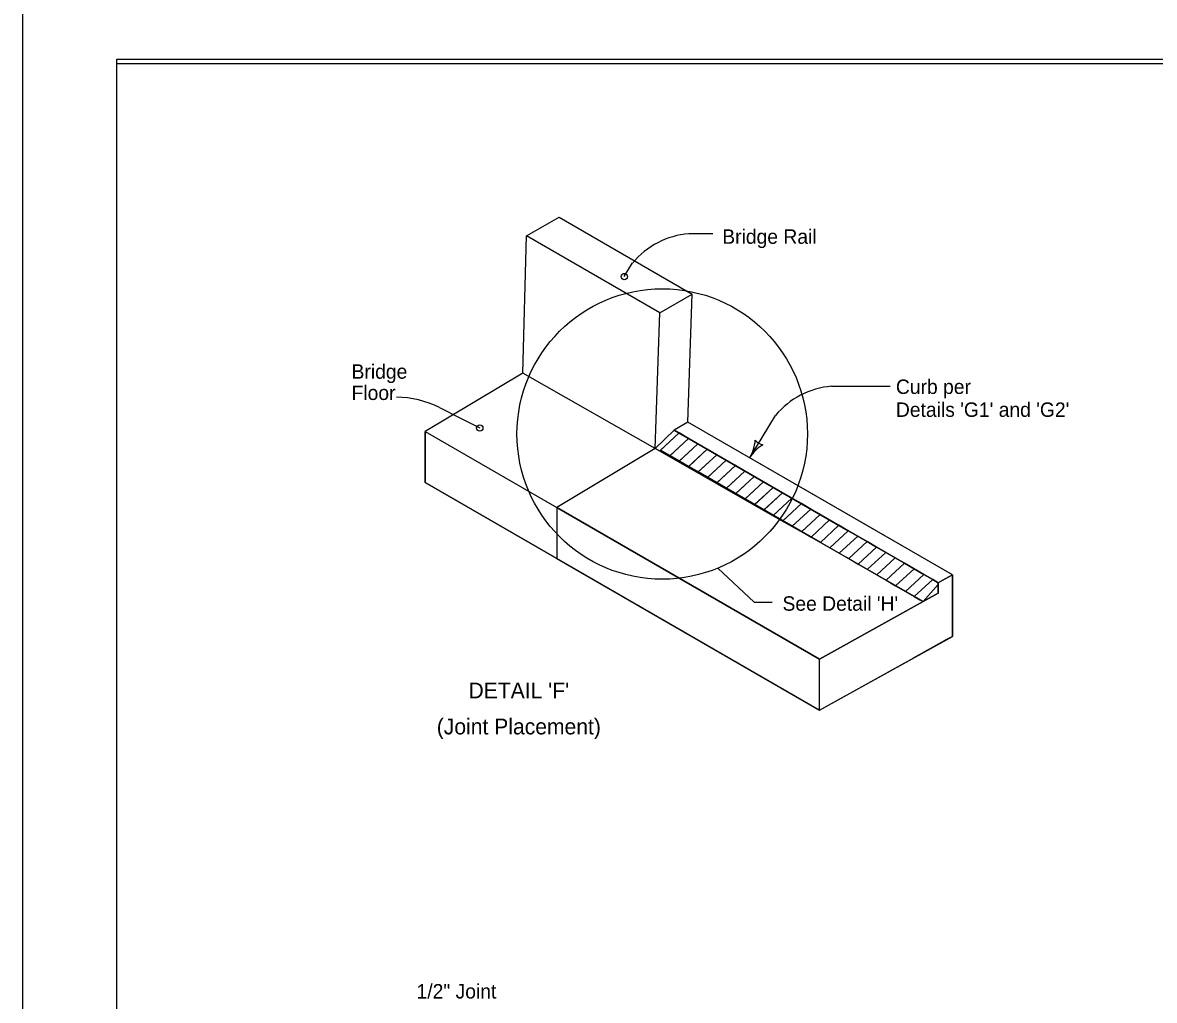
# Model space of a CAD drawing. Extents: x 10028 to 81668, y 6395 to 11634.
# Drawn here: x 24428 to 25683, y 8900 to 9984 of the extents above; entities that cross this region are included whole.
import ezdxf

# ---------------------------------------------------------------- set-up
doc = ezdxf.new("R2010")
doc.units = 0
for name, color, linetype in [('Default', 7, 'Continuous'), ('dsnCellElements', 7, 'Continuous'), ('dsnstdblockInterim', 7, 'Continuous'), ('dsnStdBlockNotModified', 7, 'Continuous'), ('dsnStdDimension', 7, 'Continuous'), ('dsnStgShadingPropPav', 7, 'Continuous'), ('ShtPlotIdentification', 7, 'Continuous')]:
    doc.layers.add(name, color=color, linetype=linetype)

msp = doc.modelspace()

# ---------------------------------------------------------------- linework, layer by layer
at = {"layer": 'Default'}
msp.add_lwpolyline([(24532.5, 9944), (27667.6, 9944), (27667.6, 7924), (24532.5, 7924)], close=True, dxfattribs=at)
at = {"layer": 'dsnstdblockInterim'}
msp.add_lwpolyline([(24532.5, 9939), (27667.5, 9939), (27667.5, 7929), (24532.5, 7929)], close=True, dxfattribs=at)
at = {"layer": 'dsnStdBlockNotModified'}
for centre, radius, start, end in [((25198.2, 9523.7), 42.5, 328.7108, 356.7833), ((25270.8, 9479.5), 42.5, 120.6383, 148.7108), ((25253, 9532), 16.4, 220.9775, 256.4442)]:
    msp.add_arc(centre, radius, start, end, dxfattribs=at)
at = {"layer": 'dsnStdDimension'}
msp.add_lwpolyline([(24428, 7824.5), (27772, 7824.5), (27772, 10408.5), (24428, 10408.5)], close=True, dxfattribs=at)
at = {"layer": 'dsnStgShadingPropPav'}
for centre in [(25095.4, 9702.6), (24935.1, 9534.7)]:
    msp.add_circle(centre, 3.54, dxfattribs=at)
at = {"layer": 'ShtPlotIdentification'}
for p, q in [((25023, 9768.4), (25170.6, 9683.1)), ((24982.9, 9595.6), (24987.1, 9747.7)), ((25134.8, 9662.4), (24987.1, 9747.7)), ((25166.9, 9750.3), (25193.8, 9750.3)), ((25095.4, 9702.6), (25104.7, 9717.9)), ((25165.9, 9541.2), (25170.6, 9683.1)), ((25129.8, 9511.8), (25134.8, 9662.4)), ((25129.8, 9511.8), (24982.9, 9595.6)), ((25129.8, 9511.8), (24982.9, 9595.6)), ((25325.3, 9581), (25390.5, 9581)), ((24890.4, 9557.3), (24913.7, 9545.5)), ((24913.7, 9545.5), (24935.1, 9534.7)), ((25165.9, 9541.2), (25150.7, 9532.2)), ((25459.4, 9371.7), (25165.9, 9541.2)), ((25234.5, 9501.6), (25263.1, 9548.6)), ((24874.6, 9530.8), (24874.6, 9474.2)), ((24874.6, 9530.8), (25311.9, 9278.3)), ((25156.2, 9529.1), (25134.6, 9509.1)), ((25156.2, 9529.1), (25135.7, 9510.1)), ((25150.7, 9532.2), (25343.9, 9420.6)), ((25443.7, 9363), (25150.7, 9532.2)), ((25166.6, 9523), (25156.2, 9529.1)), ((25166.6, 9523), (25145.1, 9503.1)), ((25166.6, 9523), (25146.2, 9504.1)), ((25146.2, 9504.1), (25166.6, 9523)), ((25177, 9517), (25155.5, 9497.1)), ((25177, 9517), (25156.6, 9498.1)), ((25156.6, 9498.1), (25177, 9517)), ((25177, 9517), (25166.6, 9523)), ((25187.4, 9511), (25177, 9517)), ((25129.8, 9511.8), (25020.6, 9446.5)), ((25260.3, 9437.3), (25129.8, 9511.8)), ((25135.7, 9510.1), (25146.2, 9504.1)), ((25146.2, 9504.1), (25156.6, 9498.1)), ((25187.4, 9511), (25166, 9491.1)), ((25187.4, 9511), (25167, 9492)), ((25167, 9492), (25187.4, 9511)), ((25197.9, 9505), (25176.5, 9485.1)), ((25197.9, 9505), (25177.4, 9486)), ((25177.4, 9486), (25197.9, 9505)), ((25197.9, 9505), (25187.4, 9511)), ((25208.3, 9498.9), (25197.9, 9505)), ((25156.6, 9498.1), (25167, 9492)), ((25167, 9492), (25177.4, 9486)), ((25208.3, 9498.9), (25187, 9479.1)), ((25208.3, 9498.9), (25187.9, 9480)), ((25187.9, 9480), (25208.3, 9498.9)), ((25218.7, 9492.9), (25197.4, 9473.2)), ((25218.7, 9492.9), (25198.3, 9474)), ((25198.3, 9474), (25218.7, 9492.9)), ((25218.7, 9492.9), (25208.3, 9498.9)), ((25229.2, 9486.9), (25218.7, 9492.9)), ((25177.4, 9486), (25187.9, 9480)), ((25187.9, 9480), (25198.3, 9474)), ((25229.2, 9486.9), (25207.9, 9467.2)), ((25229.2, 9486.9), (25208.7, 9467.9)), ((25208.7, 9467.9), (25229.2, 9486.9)), ((25239.6, 9480.9), (25218.4, 9461.2)), ((25239.6, 9480.9), (25219.2, 9461.9)), ((25219.2, 9461.9), (25239.6, 9480.9)), ((25239.6, 9480.9), (25229.2, 9486.9)), ((25250, 9474.8), (25239.6, 9480.9)), ((24874.6, 9474.2), (25311.9, 9221.7)), ((25311.9, 9221.7), (24874.6, 9474.2)), ((25198.3, 9474), (25208.7, 9467.9)), ((25208.7, 9467.9), (25219.2, 9461.9)), ((25250, 9474.8), (25228.9, 9455.2)), ((25250, 9474.8), (25229.6, 9455.9)), ((25229.6, 9455.9), (25250, 9474.8)), ((25260.5, 9468.8), (25239.3, 9449.2)), ((25260.5, 9468.8), (25240, 9449.9)), ((25240, 9449.9), (25260.5, 9468.8)), ((25260.5, 9468.8), (25250, 9474.8)), ((25270.9, 9462.8), (25260.5, 9468.8)), ((25219.2, 9461.9), (25229.6, 9455.9)), ((25229.6, 9455.9), (25240, 9449.9)), ((25270.9, 9462.8), (25249.8, 9443.3)), ((25270.9, 9462.8), (25250.5, 9443.9)), ((25250.5, 9443.9), (25270.9, 9462.8)), ((25281.3, 9456.8), (25260.3, 9437.3)), ((25281.3, 9456.8), (25260.9, 9437.8)), ((25260.9, 9437.8), (25281.3, 9456.8)), ((25281.3, 9456.8), (25270.9, 9462.8)), ((25291.8, 9450.8), (25281.3, 9456.8)), ((25020.6, 9446.5), (25020.6, 9389.9)), ((25240, 9449.9), (25250.5, 9443.9)), ((25250.5, 9443.9), (25260.9, 9437.8)), ((25291.8, 9450.8), (25270.9, 9431.4)), ((25291.8, 9450.8), (25271.3, 9431.8)), ((25271.3, 9431.8), (25291.8, 9450.8)), ((25302.2, 9444.7), (25281.4, 9425.4)), ((25302.2, 9444.7), (25281.8, 9425.8)), ((25281.8, 9425.8), (25302.2, 9444.7)), ((25302.2, 9444.7), (25291.8, 9450.8)), ((25312.6, 9438.7), (25302.2, 9444.7)), ((25313.1, 9407.7), (25260.3, 9437.3)), ((25260.9, 9437.8), (25271.3, 9431.8)), ((25271.3, 9431.8), (25281.8, 9425.8)), ((25312.6, 9438.7), (25292, 9419.5)), ((25312.6, 9438.7), (25292.2, 9419.8)), ((25292.2, 9419.8), (25312.6, 9438.7)), ((25323.1, 9432.7), (25302.6, 9413.7)), ((25323.1, 9432.7), (25302.6, 9413.7)), ((25302.6, 9413.7), (25323.1, 9432.7)), ((25323.1, 9432.7), (25312.6, 9438.7)), ((25333.5, 9426.7), (25323.1, 9432.7)), ((25459.4, 9371.7), (25349.2, 9435.4)), ((25281.8, 9425.8), (25292.2, 9419.8)), ((25292.2, 9419.8), (25302.6, 9413.7)), ((25333.5, 9426.7), (25313.1, 9407.7)), ((25333.5, 9426.7), (25313.1, 9407.7)), ((25313.1, 9407.7), (25333.5, 9426.7)), ((25323.5, 9401.7), (25343.9, 9420.6)), ((25343.9, 9420.6), (25323.5, 9401.7)), ((25343.9, 9420.6), (25323.5, 9401.7)), ((25343.9, 9420.6), (25333.5, 9426.7)), ((25354.3, 9414.6), (25343.9, 9420.6)), ((25343.9, 9420.6), (25354.3, 9414.6)), ((25302.6, 9413.7), (25313.1, 9407.7)), ((25313.1, 9407.7), (25323.5, 9401.7)), ((25423.3, 9344.1), (25313.1, 9407.7)), ((25426.8, 9342), (25313.1, 9407.7)), ((25333.9, 9395.7), (25354.3, 9414.6)), ((25354.3, 9414.6), (25333.9, 9395.7)), ((25354.3, 9414.6), (25333.9, 9395.7)), ((25344.3, 9389.7), (25364.7, 9408.6)), ((25364.7, 9408.6), (25344.3, 9389.7)), ((25364.7, 9408.6), (25344.3, 9389.7)), ((25364.7, 9408.6), (25354.3, 9414.6)), ((25354.3, 9414.6), (25364.7, 9408.6)), ((25354.7, 9383.7), (25375.1, 9402.6)), ((25375.1, 9402.6), (25354.7, 9383.7)), ((25375.1, 9402.6), (25354.7, 9383.7)), ((25375.1, 9402.6), (25364.7, 9408.6)), ((25364.7, 9408.6), (25375.1, 9402.6)), ((25323.5, 9401.7), (25333.9, 9395.7)), ((25333.9, 9395.7), (25344.3, 9389.7)), ((25385.4, 9396.7), (25365.3, 9378.1)), ((25375.5, 9371.7), (25395.9, 9390.6)), ((25395.9, 9390.6), (25375.5, 9371.7)), ((25395.9, 9390.6), (25375.5, 9371.7)), ((25406.3, 9384.6), (25395.9, 9390.6)), ((25395.9, 9390.6), (25406.3, 9384.6)), ((25199.3, 9379.3), (25239.6, 9341.3)), ((25344.3, 9389.7), (25354.7, 9383.7)), ((25354.7, 9383.7), (25375.5, 9371.7)), ((25385.9, 9365.7), (25406.3, 9384.6)), ((25406.3, 9384.6), (25385.9, 9365.7)), ((25406.3, 9384.6), (25385.9, 9365.7)), ((25416.9, 9378.5), (25396.4, 9359.6)), ((25375.5, 9371.7), (25385.9, 9365.7)), ((25385.9, 9365.7), (25396.4, 9359.6)), ((25427.8, 9372.2), (25407.4, 9353.3)), ((25417.1, 9347.6), (25437.5, 9366.6)), ((25437.5, 9366.6), (25417.1, 9347.6)), ((25437.5, 9366.6), (25417.1, 9347.6)), ((25443.7, 9363), (25437.5, 9366.6)), ((25437.5, 9366.6), (25443.7, 9363)), ((25443.7, 9363), (25451.5, 9367.4)), ((25451.5, 9367.4), (25443.7, 9363)), ((25451.5, 9367.4), (25459.4, 9371.7)), ((25459.4, 9371.7), (25451.5, 9367.4)), ((25396.4, 9359.6), (25417.1, 9347.6)), ((25426.8, 9342), (25443.7, 9361.1)), ((25443.7, 9361.1), (25426.8, 9342)), ((25426.8, 9342), (25443.7, 9361.1)), ((25443.7, 9361.1), (25443.7, 9363)), ((25443.7, 9351.4), (25443.7, 9363)), ((25443.7, 9351.4), (25443.7, 9361.1)), ((25239.6, 9341.3), (25259.5, 9341.3)), ((25311.9, 9278.3), (25443.7, 9351.4)), ((25417.1, 9347.6), (25423.3, 9344.1)), ((25423.3, 9344.1), (25426.8, 9342)), ((25426.8, 9342), (25443.7, 9351.4)), ((25459.4, 9303.5), (25451.5, 9299.1)), ((25311.9, 9221.7), (25436.5, 9290.8)), ((25416.3, 9279.6), (25451.5, 9299.1)), ((25311.9, 9221.7), (25311.9, 9278.3))]:
    msp.add_line(p, q, dxfattribs=at)
for points in [[(24987.1, 9747.7), (25023, 9768.4)], [(25134.8, 9662.4), (25170.6, 9683.1)], [(24982.9, 9595.6), (24874.6, 9530.8)], [(25165.9, 9541.2), (25150.7, 9532.2), (25129.8, 9511.8)], [(25165.9, 9541.2), (25150.7, 9532.2), (25129.8, 9511.8)], [(25349.2, 9435.4), (25349.2, 9435.4), (25165.9, 9541.2)], [(24874.6, 9474.2), (24874.6, 9530.8)], [(24874.6, 9474.2), (24874.6, 9530.8)], [(25313.1, 9407.7), (25260.3, 9437.3)], [(25395.9, 9390.6), (25385.4, 9396.7), (25375.1, 9402.6)], [(25375.1, 9402.6), (25385.4, 9396.7), (25395.9, 9390.6)], [(25437.5, 9366.6), (25427.8, 9372.2), (25406.3, 9384.6)], [(25406.3, 9384.6), (25427.8, 9372.2), (25437.5, 9366.6)], [(25459.4, 9371.7), (25459.4, 9303.5)]]:
    msp.add_lwpolyline(points, dxfattribs=at)
for points in [[(25129.8, 9511.8), (25020.6, 9446.5), (25311.9, 9278.3), (25426.8, 9342), (25313.1, 9407.7), (25177.4, 9486), (25135.7, 9510.1), (25156.2, 9529.1), (25150.7, 9532.2)], [(25311.9, 9278.3), (25426.8, 9342), (25313.1, 9407.7), (25129.8, 9511.8), (25020.6, 9446.5)], [(25020.6, 9446.5), (25020.6, 9389.9), (25311.9, 9221.7), (25459.4, 9303.5), (25459.4, 9371.7), (25443.7, 9363), (25443.7, 9351.4), (25311.9, 9278.3)]]:
    msp.add_lwpolyline(points, close=True, dxfattribs=at)
msp.add_circle((25137.5, 9528), 161.1, dxfattribs=at)
for centre, radius, start, end in [((25174.6, 9659.5), 91, 94.8409, 140.1467), ((25333, 9490.3), 91, 94.8409, 140.1467), ((24842.7, 9462.8), 105.9, 63.2177, 90)]:
    msp.add_arc(centre, radius, start, end, dxfattribs=at)

# ---------------------------------------------------------------- texts
at = {"layer": 'dsnCellElements'}
for s, height, p in [('(Joint Placement)', 17.5, (24887.4, 9194.7)), ('1/2" Joint', 16, (24865, 8901.7))]:
    msp.add_text(s, height=height, dxfattribs=at).set_placement(p)
at = {"layer": 'ShtPlotIdentification'}
for s, height, p in [('Bridge Rail ', 16, (25204.1, 9739)), ('Bridge', 16, (24792.9, 9589.3)), ('Floor', 16, (24792.9, 9565.7)), ('Curb per', 16, (25396.7, 9572.4)), ("Details 'G1' and 'G2'", 16, (25396.7, 9547)), ("See Detail 'H'", 16, (25270.9, 9331.9)), ("DETAIL 'F'", 17.5, (24922.6, 9234.7))]:
    msp.add_text(s, height=height, dxfattribs=at).set_placement(p)

doc.saveas('drawing.dxf')
